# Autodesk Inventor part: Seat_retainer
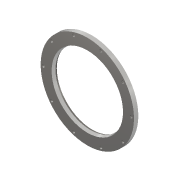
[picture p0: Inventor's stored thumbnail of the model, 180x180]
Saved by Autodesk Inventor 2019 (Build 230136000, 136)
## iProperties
Created: 2019-09
Part Number: Seat_retainer
Material: Steel, Cast
Document SubType Name: Modeling
Designer: Admin
Density: 7.85 g/cm^3
Appearance: Semi-Polished
Author: Admin
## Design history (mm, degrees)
sketch "Sketch1"
  geometry: L1 (-162, -1343.33)-(-162, 1627.083); L2 (-162, 19.8)-(-139.94, 19.8); L3 (-123.9, 34.8)-(-162, 34.8); L4 (-162, 34.8)-(-162, 19.8); L5 (-76.461, 23.8)-(-192.203, 23.8); L6 (-122.5, 4.825)-(-122.5, 79.685); L7 (-123.9, 4.825)-(-123.9, 83.319); L8 (-121.3, 23.8)-(-123.9, 34.8); L9 (0, -1937.413)-(0, 2221.166) reference; L10 (-141.514, 18.304)-(-141.131, 19.8); L11 (-144, 19.8)-(-141.131, 19.8); L12 (-144, 14.657)-(-138.677, 13.296); L13 (-137.959, 16.105)-(-139.413, 16.477); L14 (-137.959, 16.105)-(-139.413, 16.477); L15 (-139.598, 15.75)-(-139.413, 16.477); L16 (-139.413, 16.477)-(-139.598, 15.75); L17 (-139.598, 15.75)-(-140.89, 16.08); L18 (-139.598, 15.75)-(-140.89, 16.08); L19 (-140.89, 16.08)-(-141.514, 18.304); L20 (-138.608, 19.625)-(-138.793, 18.899); L21 (-135.701, 18.882)-(-135.887, 18.156); L22 (-135.701, 18.882)-(-137.154, 19.254); L23 (-135.701, 18.882)-(-137.154, 19.254); L24 (-135.239, 14.635)-(-135.053, 15.362); L25 (-135.239, 14.635)-(-135.053, 15.362); L26 (-135.053, 15.362)-(-136.506, 15.733); L27 (-135.053, 15.362)-(-136.506, 15.733); L28 (-136.692, 15.007)-(-136.506, 15.733); L29 (-136.506, 15.733)-(-136.692, 15.007); L30 (-136.692, 15.007)-(-138.145, 15.378); L31 (-138.145, 15.378)-(-137.959, 16.105); L32 (-138.145, 15.378)-(-137.959, 16.105); L33 (-136.692, 15.007)-(-138.145, 15.378); L34 (-134.434, 17.784)-(-135.887, 18.156); L35 (-137.154, 19.254)-(-137.34, 18.527); L36 (-137.34, 18.527)-(-138.793, 18.899); L37 (-133.785, 14.264)-(-135.239, 14.635); L38 (-133.785, 14.264)-(-135.239, 14.635); L39 (-133.785, 14.264)-(-133.6, 14.99); L40 (-133.6, 14.99)-(-133.785, 14.264); L41 (-132.332, 13.892)-(-132.146, 14.619); L42 (-132.332, 13.892)-(-132.146, 14.619); L43 (-132.146, 14.619)-(-133.6, 14.99); L44 (-132.146, 14.619)-(-133.6, 14.99); L45 (-129.24, 13.876)-(-130.693, 14.247); L46 (-129.425, 13.149)-(-129.24, 13.876); L47 (-129.888, 17.396)-(-131.341, 17.768); L48 (-129.888, 17.396)-(-130.074, 16.67); L49 (-128.621, 16.298)-(-130.074, 16.67); L50 (-128.435, 17.025)-(-128.621, 16.298); L51 (-130.879, 13.521)-(-130.693, 14.247); L52 (-130.693, 14.247)-(-130.879, 13.521); L53 (-129.24, 13.876)-(-130.693, 14.247); L54 (-128.03, 12.81)-(-128.528, 12.92); L55 (-129.425, 13.149)-(-129.24, 13.876); L56 (-127.486, 16.782)-(-128.435, 17.025); L57 (-131.341, 17.768)-(-131.527, 17.041); L58 (-128.477, 12.907)-(-129.425, 13.149); L59 (-131.527, 17.041)-(-132.98, 17.413); L60 (-129.888, 17.396)-(-131.341, 17.768); L61 (-132.795, 18.139)-(-132.98, 17.413); L62 (-132.795, 18.139)-(-134.248, 18.511); L63 (-134.248, 18.511)-(-134.434, 17.784); L64 (-144, 19.8)-(-144, 14.657)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; A1 r 4.17 centre (-122.148, 13.353) between (-125.656, 11.098) and (-123.181, 9.313); A2 r 7.167 centre (-123.225, 16.744) between (-129.425, 13.149) and (-125, 9.8); A3 r 4 centre (-126.495, 20.658) between (-127.486, 16.782) and (-124.45, 17.22); A4 r 4 centre (-129.02, 8.935) between (-125.656, 11.098) and (-128.03, 12.81); A5 r 7.167 centre (-124.72, 10.896) between (-122.945, 17.839) and (-128.435, 17.025); 7 further points
  constraints: 188 end point, 19 perpendicular, 11 point on line, 10 point on circle, 8 collinear, 7 tangent, 6 horizontal, 5 centre point, 4 parallel, 3 vertical, 2 symmetric about line, 1 midpoint, 5 other
  dimensions: "d3" = 162 distance from line of L1 point (0, 0); "d6" = 11 distance between parallel lines of L3 L5; "d7" = 39.5 distance between parallel lines of L6 L1; "d8" = 38.1 distance between parallel lines of L7 L1; "d10" = 40.7 distance from line of L8.start L4; "d25" = 90 deg angle of L46 L58; "d26" = 7.16694 radius of A2 (derived); "d27" = 1.5 distance between parallel lines of L51 L46; "d28" = 1.45327 horizontal distance of L51.start L41.start; "d29" = 1.5 distance between parallel lines of L39 L41; "d30" = 1.45327 horizontal distance of L37.start L24.start; "d31" = 1.5 distance between parallel lines of L28 L24; "d32" = 1.45327 horizontal distance of L28.start L30.end; "d33" = 1.5 distance between parallel lines of L15 L31; "d34" = 1.29211 horizontal distance of L15.start L17.end; "d35" = 0.75 distance between parallel lines of L43 L38; "d36" = 0.75 distance between parallel lines of L26 L33; "d37" = 0.75 distance between parallel lines of L13 L18; "d38" = 120 deg angle of L19 L17; "d39" = 150 deg angle of L10 L19 (derived); "d40" = 2 distance between parallel lines of L30 L71; "d41" = 4.14896 distance between parallel lines of L12 L71; "d42" = 4.149 distance between parallel lines of L71 L72; "d43" = 1.5 distance between parallel lines of L48 L85; "d44" = 1.45327 horizontal distance of L47.start L47.end; "d45" = 1.5 distance between parallel lines of L79 L57; "d46" = 1.5 distance between parallel lines of L81 L79; "d47" = 1.5 distance between parallel lines of L21 L63; "d48" = 1.5 distance between parallel lines of L35 L21; "d49" = 1.5 distance between parallel lines of L20 L35; "d50" = 7.16694 radius of A5; "d51" = 0.75 distance between parallel lines of L59 L47; "d52" = 0.75 distance between parallel lines of L34 L62; "d53" = 0.75 distance between parallel lines of L36 L22; "d54" = 1.29211 horizontal distance of L20.start L69.end; "d55" = 15 distance between parallel lines of L3 L2; "d56" = 15 distance between parallel lines of L92 L3
revolve "Revolution1" sketch "Sketch1" stored, may be unused: angle "d11" = 90 deg
sketch "Sketch3"
  geometry: L1 (0, 0)-(152.5, 0); L2 (152.5, 0)-(152.5, -76.49); L3 (152.5, -76.49)-(0, -76.49); L4 (0, -76.49)-(0, 0); 1 further point
  constraints: 8 end point, 2 parallel, 1 coincident, 1 horizontal, 1 perpendicular
  dimensions: "d57" = 152.5 distance between parallel lines of L2 L4; "d58" = 76.48978 distance between parallel lines of L3 L1
hole "Hole2" sketch "Sketch3" at (152.5, 0) diameter "d59" = 5; stored, may be unused: countersink angle "d63" = 90 deg, drill point angle "d65" = 118 deg; dims "d60" = 6, "d61" = 10, "d62" = 5, "d64" = 8
pattern_circular "Circular Pattern2" dims angle "d67" = 360 deg
body "Solid1"
other parameters: "d2" = 19.8, "d9" = 15
